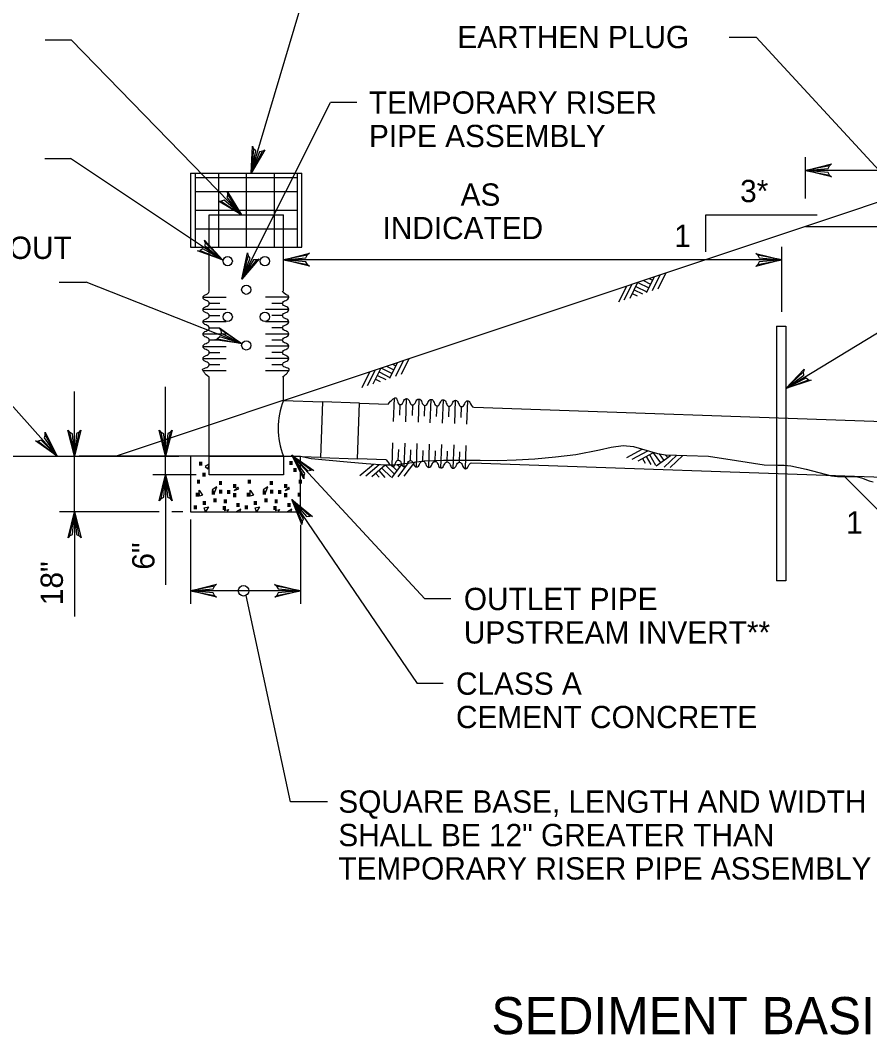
# Model space of a CAD drawing. Extents: x 636462 to 639890, y 299944 to 300538.
# Drawn here: x 638284.1 to 638398.4, y 300298.5 to 300434.9 of the extents above; entities that cross this region are included whole.
import ezdxf

# ---------------------------------------------------------------- set-up
doc = ezdxf.new("R2010")
doc.units = 0
doc.layers.add('Default', color=7, linetype='Continuous')

msp = doc.modelspace()

# ---------------------------------------------------------------- linework, layer by layer
at = {"layer": 'Default'}
for p, q in [((638315.17, 300414.4), (638326.63, 300452.77)), ((638379.5, 300432.69), (638383.11, 300432.69)), ((638399.69, 300414.74), (638383.11, 300432.69)), ((638287.46, 300432.33), (638290.96, 300432.33)), ((638313.87, 300408.78), (638290.96, 300432.33)), ((638313.89, 300400.13), (638325.85, 300423.89)), ((638329.39, 300423.89), (638325.85, 300423.89)), ((638287.41, 300416.33), (638290.85, 300416.33)), ((638311.33, 300402.72), (638290.85, 300416.33)), ((638389.77, 300410.96), (638389.77, 300416.55)), ((638409.6, 300414.74), (638389.77, 300414.74)), ((638307.01, 300414.4), (638322, 300414.4)), ((638307.01, 300414.4), (638307.01, 300404.41)), ((638307.64, 300414.4), (638307.64, 300404.41)), ((638307.64, 300413.78), (638321.38, 300413.78)), ((638310.76, 300414.4), (638310.76, 300404.41)), ((638314.51, 300414.4), (638314.51, 300404.41)), ((638318.26, 300414.4), (638318.26, 300404.41)), ((638321.38, 300404.41), (638321.38, 300414.4)), ((638322, 300404.41), (638322, 300414.4)), ((638307.64, 300411.91), (638321.38, 300411.91)), ((638307.64, 300409.41), (638321.38, 300409.41)), ((638309.51, 300398.49), (638309.51, 300408.78)), ((638309.51, 300408.78), (638319.5, 300408.78)), ((638319.5, 300398.51), (638319.5, 300408.78)), ((638307.64, 300406.91), (638321.38, 300406.91)), ((638307.01, 300404.41), (638322, 300404.41)), ((638319.5, 300400.26), (638319.5, 300404.46)), ((638386.56, 300395.74), (638386.56, 300404.46)), ((638386.56, 300402.71), (638319.5, 300402.71)), ((638289.35, 300399.72), (638292.94, 300399.72)), ((638313.85, 300391.48), (638292.94, 300399.72)), ((638366.15, 300397.57), (638367.21, 300399.7)), ((638367.18, 300399.69), (638368.68, 300398.94)), ((638367.95, 300399.95), (638368.92, 300399.46)), ((638368.36, 300398.31), (638369.43, 300400.45)), ((638368.72, 300400.21), (638369.19, 300399.97)), ((638369.17, 300398.58), (638370.22, 300400.69)), ((638369.94, 300398.84), (638370.99, 300400.94)), ((638364.64, 300397.07), (638365.7, 300399.19)), ((638365.38, 300397.32), (638366.44, 300399.45)), ((638366.7, 300398.69), (638367.82, 300398.13)), ((638366.93, 300399.15), (638368.4, 300398.41)), ((638387.1, 300385.4), (638408.53, 300398.44)), ((638311.82, 300397.67), (638308.69, 300397.67)), ((638320.22, 300397.68), (638317.09, 300397.68)), ((638366.45, 300398.18), (638367.09, 300397.86)), ((638311.82, 300396.02), (638308.69, 300396.02)), ((638310.95, 300396.84), (638309.51, 300396.84)), ((638320.22, 300396.03), (638317.09, 300396.03)), ((638319.4, 300396.86), (638317.96, 300396.86)), ((638311.82, 300394.37), (638308.69, 300394.37)), ((638310.95, 300395.19), (638309.51, 300395.19)), ((638320.22, 300394.39), (638317.09, 300394.39)), ((638319.4, 300395.21), (638317.96, 300395.21)), ((638310.95, 300393.54), (638309.51, 300393.54)), ((638319.4, 300393.56), (638317.96, 300393.56)), ((638385.85, 300393.79), (638387.1, 300393.79)), ((638385.85, 300393.79), (638385.85, 300359.54)), ((638387.1, 300393.79), (638387.1, 300359.54)), ((638311.82, 300392.72), (638308.69, 300392.72)), ((638310.95, 300391.89), (638309.51, 300391.89)), ((638320.22, 300392.74), (638317.09, 300392.74)), ((638319.4, 300391.91), (638317.96, 300391.91)), ((638308.69, 300391.07), (638311.82, 300391.07)), ((638309.51, 300390.24), (638310.95, 300390.24)), ((638320.22, 300391.09), (638317.09, 300391.09)), ((638319.4, 300390.26), (638317.96, 300390.26)), ((638311.82, 300389.42), (638308.69, 300389.42)), ((638320.22, 300389.44), (638317.09, 300389.44)), ((638333.81, 300386.8), (638334.88, 300388.93)), ((638334.17, 300388.69), (638334.64, 300388.46)), ((638334.62, 300387.07), (638335.67, 300389.17)), ((638335.39, 300387.32), (638336.44, 300389.43)), ((638311.82, 300387.77), (638308.69, 300387.77)), ((638310.95, 300388.6), (638309.51, 300388.6)), ((638320.22, 300387.79), (638317.09, 300387.79)), ((638319.4, 300388.61), (638317.96, 300388.61)), ((638330.09, 300385.55), (638331.15, 300387.67)), ((638330.83, 300385.8), (638331.9, 300387.93)), ((638331.6, 300386.06), (638332.66, 300388.19)), ((638332.39, 300387.63), (638333.85, 300386.9)), ((638332.63, 300388.17), (638334.13, 300387.42)), ((638333.4, 300388.43), (638334.38, 300387.94)), ((638309.51, 300376.3), (638309.51, 300386.95)), ((638319.5, 300383.8), (638319.5, 300386.97)), ((638331.9, 300386.66), (638332.54, 300386.34)), ((638332.16, 300387.17), (638333.27, 300386.62)), ((638291.38, 300368.81), (638291.38, 300385.01)), ((638303.66, 300373.81), (638303.66, 300385.62)), ((638289.06, 300376.3), (638282.07, 300384.14)), ((638319.45, 300383.78), (638309.51, 300380.47)), ((638319.5, 300383.8), (638324.76, 300383.62)), ((638329.75, 300383.45), (638333.59, 300383.31)), ((638334.33, 300380.98), (638334.44, 300384.11)), ((638335.18, 300381.82), (638335.23, 300383.25)), ((638335.98, 300380.92), (638336.09, 300384.05)), ((638337.73, 300383.99), (638337.62, 300380.86)), ((638339.27, 300380.8), (638339.38, 300383.93)), ((638340.92, 300380.75), (638341.03, 300383.88)), ((638342.57, 300380.69), (638342.68, 300383.82)), ((638344.21, 300380.63), (638344.32, 300383.76)), ((638336.88, 300383.2), (638336.83, 300381.76)), ((638338.48, 300381.7), (638338.53, 300383.14)), ((638340.13, 300381.64), (638340.18, 300383.08)), ((638341.77, 300381.59), (638341.82, 300383.02)), ((638343.42, 300381.53), (638343.47, 300382.97)), ((638345.12, 300382.91), (638458.99, 300378.93)), ((638309.51, 300380.47), (638297.02, 300376.3)), ((638334.12, 300374.97), (638334.23, 300378.1)), ((638335.77, 300374.91), (638335.88, 300378.04)), ((638337.41, 300374.85), (638337.52, 300377.99)), ((638339.06, 300374.8), (638339.17, 300377.93)), ((638340.71, 300374.74), (638340.82, 300377.87)), ((638342.36, 300374.68), (638342.47, 300377.81)), ((638320.64, 300376.46), (638338.54, 300357.1)), ((638334.97, 300375.76), (638335.02, 300377.2)), ((638336.62, 300375.71), (638336.67, 300377.14)), ((638338.27, 300375.65), (638338.32, 300377.09)), ((638339.91, 300375.59), (638339.96, 300377.03)), ((638341.56, 300375.53), (638341.61, 300376.97)), ((638343.21, 300375.48), (638343.26, 300376.91)), ((638344.01, 300374.62), (638344.11, 300377.75)), ((638365.71, 300376.12), (638367.78, 300377.26)), ((638366.46, 300375.9), (638368.55, 300377.04)), ((638367.24, 300375.67), (638369.32, 300376.82)), ((638368.78, 300376.52), (638369.58, 300375.08)), ((638369.28, 300376.76), (638370.26, 300375.4)), ((638370.07, 300376.63), (638370.71, 300375.74)), ((638370.75, 300374.81), (638372.45, 300376.43)), ((638370.88, 300376.49), (638371.24, 300376.12)), ((638371.56, 300374.79), (638373.26, 300376.41)), ((638280.08, 300376.3), (638305.45, 300376.3)), ((638307.76, 300376.3), (638292.04, 300376.3)), ((638309.51, 300375.23), (638308.98, 300374.9)), ((638309.32, 300374.6), (638309.51, 300375.09)), ((638324.5, 300376.13), (638319.5, 300376.3)), ((638333.32, 300375.82), (638329.49, 300375.96)), ((638329.81, 300373.71), (638331.62, 300375.24)), ((638330.59, 300373.65), (638332.41, 300375.18)), ((638331.4, 300373.58), (638333.21, 300375.12)), ((638333.18, 300375.12), (638334.39, 300373.95)), ((638333.99, 300375.13), (638334.77, 300374.37)), ((638334.1, 300373.39), (638335.54, 300375.3)), ((638334.8, 300375.18), (638335.22, 300374.87)), ((638334.95, 300373.51), (638336.36, 300375.39)), ((638335.75, 300373.62), (638337.17, 300375.5)), ((638344.86, 300375.42), (638458.72, 300371.44)), ((638367.83, 300376), (638368.17, 300375.37)), ((638368.34, 300376.27), (638368.94, 300375.18)), ((638369.68, 300374.99), (638371.62, 300376.39)), ((638307.76, 300373.81), (638301.92, 300373.81)), ((638303.66, 300373.81), (638303.66, 300359.02)), ((638308.98, 300374.9), (638309.32, 300374.6)), ((638331.91, 300374.01), (638332.37, 300373.47)), ((638332.35, 300374.38), (638333.15, 300373.43)), ((638332.78, 300374.67), (638333.96, 300373.53)), ((638320.64, 300370.47), (638337.49, 300345.71)), ((638302.77, 300368.81), (638289.39, 300368.81)), ((638291.38, 300368.81), (638291.38, 300354.76)), ((638305.96, 300368.81), (638304.5, 300368.81)), ((638308.85, 300369.36), (638309.44, 300369.48)), ((638309.01, 300368.81), (638308.85, 300369.36)), ((638309.44, 300369.48), (638309.03, 300368.81)), ((638311.55, 300369), (638312.13, 300369.11)), ((638312.13, 300369.11), (638311.95, 300368.81)), ((638313.78, 300369.17), (638313.2, 300368.81)), ((638313.64, 300368.81), (638313.78, 300369.17)), ((638315.71, 300369.36), (638316.29, 300369.48)), ((638315.87, 300368.81), (638315.71, 300369.36)), ((638316.29, 300369.48), (638315.89, 300368.81)), ((638318.41, 300369), (638318.99, 300369.11)), ((638318.99, 300369.11), (638318.81, 300368.81)), ((638320.64, 300369.17), (638320.06, 300368.81)), ((638320.5, 300368.81), (638320.64, 300369.17)), ((638307.01, 300367.8), (638307.01, 300356.45)), ((638321.82, 300367.06), (638321.82, 300356.45)), ((638387.1, 300359.54), (638385.85, 300359.54)), ((638321.82, 300358.2), (638307.01, 300358.2)), ((638342.04, 300357.1), (638338.54, 300357.1)), ((638340.99, 300345.71), (638337.49, 300345.71))]:
    msp.add_line(p, q, dxfattribs=at)
for points in [[(638316.71, 300417.32), (638317, 300417.51), (638315.17, 300414.4), (638316.71, 300417.32), (638316.3, 300417.23), (638315.17, 300414.4), (638315.8, 300417.38), (638315.49, 300417.66), (638315.17, 300414.4), (638315.33, 300418.01), (638315.49, 300417.66)], [(638319.5, 300383.8), (638413.19, 300415.03), (638434.43, 300415.03), (638455.67, 300415.03)], [(638393, 300414.1), (638393.27, 300413.88), (638389.77, 300414.74), (638393, 300414.1), (638392.81, 300414.48), (638389.77, 300414.74), (638392.8, 300415), (638392.98, 300415.38), (638389.77, 300414.74), (638393.27, 300415.63), (638392.98, 300415.38)], [(638312.02, 300411.51), (638311.99, 300411.86), (638313.87, 300408.78), (638312.02, 300411.51), (638311.9, 300411.11), (638313.87, 300408.78), (638311.53, 300410.73), (638311.14, 300410.6), (638313.87, 300408.78), (638310.76, 300410.61), (638311.14, 300410.6)], [(638376.36, 300403.78), (638376.36, 300408.77), (638391.35, 300408.77)], [(638389.77, 300407.22), (638434.43, 300407.22), (638479.09, 300407.22)], [(638308.99, 300405.04), (638308.89, 300405.37), (638311.33, 300402.72), (638308.99, 300405.04), (638308.95, 300404.62), (638311.33, 300402.72), (638308.66, 300404.18), (638308.3, 300403.96), (638311.33, 300402.72), (638307.93, 300403.91), (638308.3, 300403.96)], [(638315.92, 300402.73), (638316.24, 300402.86), (638313.89, 300400.13), (638315.92, 300402.73), (638315.5, 300402.72), (638313.89, 300400.13), (638315.03, 300402.95), (638314.78, 300403.28), (638313.89, 300400.13), (638314.68, 300403.65), (638314.78, 300403.28)], [(638322.74, 300402.07), (638323.01, 300401.85), (638319.5, 300402.71), (638322.74, 300402.07), (638322.54, 300402.45), (638319.5, 300402.71), (638322.53, 300402.97), (638322.72, 300403.34), (638319.5, 300402.71), (638323, 300403.6), (638322.72, 300403.34)], [(638383.33, 300403.35), (638383.06, 300403.57), (638386.56, 300402.71), (638383.33, 300403.35), (638383.53, 300402.97), (638386.56, 300402.71), (638383.53, 300402.45), (638383.35, 300402.08), (638386.56, 300402.71), (638383.07, 300401.82), (638383.35, 300402.08)], [(638311.09, 300393.28), (638310.92, 300393.59), (638313.85, 300391.48), (638311.09, 300393.28), (638311.13, 300392.86), (638313.85, 300391.48), (638310.94, 300392.37), (638310.63, 300392.09), (638313.85, 300391.48), (638310.27, 300391.96), (638310.63, 300392.09)], [(638390.19, 300386.56), (638390.53, 300386.52), (638387.1, 300385.4), (638390.19, 300386.56), (638389.82, 300386.78), (638387.1, 300385.4), (638389.54, 300387.22), (638389.5, 300387.63), (638387.1, 300385.4), (638389.6, 300388), (638389.5, 300387.63)], [(638287.46, 300379.18), (638287.45, 300379.53), (638289.06, 300376.3), (638287.46, 300379.18), (638287.3, 300378.79), (638289.06, 300376.3), (638286.91, 300378.45), (638286.5, 300378.34), (638289.06, 300376.3), (638286.13, 300378.39), (638286.5, 300378.34)], [(638292.02, 300379.54), (638292.24, 300379.81), (638291.38, 300376.3), (638292.02, 300379.54), (638291.64, 300379.34), (638291.38, 300376.3), (638291.12, 300379.33), (638290.74, 300379.52), (638291.38, 300376.3), (638290.49, 300379.8), (638290.74, 300379.52)], [(638304.3, 300379.54), (638304.53, 300379.81), (638303.66, 300376.3), (638304.3, 300379.54), (638303.93, 300379.34), (638303.66, 300376.3), (638303.41, 300379.33), (638303.03, 300379.52), (638303.66, 300376.3), (638302.78, 300379.8), (638303.03, 300379.52)], [(638319.5, 300376.3), (638321.82, 300376.3), (638323.22, 300375.98), (638325.65, 300375.77), (638328.08, 300375.55), (638330.64, 300375.33), (638333.19, 300375.12), (638334.51, 300375.14), (638338.47, 300375.7), (638341.03, 300375.76), (638343.6, 300375.78), (638345.97, 300375.76), (638348.34, 300375.74), (638350.85, 300375.81), (638353.35, 300375.95), (638356.12, 300376.21), (638358.88, 300376.53), (638362.05, 300377.17), (638363.63, 300377.51), (638365.21, 300377.72), (638366.64, 300377.6), (638368.78, 300376.97), (638369.85, 300376.67), (638370.93, 300376.49), (638373.81, 300376.41), (638376.7, 300376.29), (638380.46, 300375.71), (638384.22, 300375.13), (638386.02, 300375.1), (638386.91, 300375.1), (638387.8, 300375.01), (638388.83, 300374.79), (638389.84, 300374.55), (638391.55, 300374.1), (638393.27, 300373.66), (638394.09, 300373.56), (638396.6, 300373.55), (638397.3, 300373.38), (638398.34, 300373.01), (638398.86, 300372.87)], [(638322.25, 300373.59), (638322.26, 300373.24), (638320.64, 300376.46), (638322.25, 300373.59), (638322.41, 300373.98), (638320.64, 300376.46), (638322.8, 300374.33), (638323.21, 300374.43), (638320.64, 300376.46), (638323.58, 300374.38), (638323.21, 300374.43)], [(638319.5, 300376.3), (638307.01, 300376.3), (638307.01, 300368.81), (638321.82, 300368.81), (638321.82, 300376.22), (638319.5, 300376.3)], [(638303.03, 300370.57), (638302.8, 300370.3), (638303.66, 300373.81), (638303.03, 300370.57), (638303.4, 300370.77), (638303.66, 300373.81), (638303.92, 300370.78), (638304.3, 300370.59), (638303.66, 300373.81), (638304.55, 300370.31), (638304.3, 300370.59)], [(638460.66, 300370.83), (638449.18, 300359.35), (638409.21, 300359.35), (638395, 300373.55)], [(638322.02, 300367.48), (638322, 300367.13), (638320.64, 300370.47), (638322.02, 300367.48), (638322.21, 300367.86), (638320.64, 300370.47), (638322.63, 300368.17), (638323.04, 300368.25), (638320.64, 300370.47), (638323.41, 300368.17), (638323.04, 300368.25)], [(638290.74, 300365.58), (638290.52, 300365.31), (638291.38, 300368.81), (638290.74, 300365.58), (638291.11, 300365.77), (638291.38, 300368.81), (638291.64, 300365.78), (638292.01, 300365.6), (638291.38, 300368.81), (638292.27, 300365.31), (638292.01, 300365.6)], [(638310.24, 300357.57), (638310.51, 300357.34), (638307.01, 300358.2), (638310.24, 300357.57), (638310.05, 300357.94), (638307.01, 300358.2), (638310.04, 300358.46), (638310.22, 300358.84), (638307.01, 300358.2), (638310.51, 300359.09), (638310.22, 300358.84)], [(638318.59, 300358.84), (638318.32, 300359.06), (638321.82, 300358.2), (638318.59, 300358.84), (638318.79, 300358.47), (638321.82, 300358.2), (638318.79, 300357.94), (638318.61, 300357.57), (638321.82, 300358.2), (638318.33, 300357.32), (638318.61, 300357.57)], [(638325.46, 300329.82), (638320.46, 300329.82), (638314.48, 300357.58)]]:
    msp.add_lwpolyline(points, dxfattribs=at)
for points in [[(638324.76, 300383.62), (638324.5, 300376.13), (638329.49, 300375.96), (638329.75, 300383.45)], [(638319.5, 300376.3), (638319.5, 300373.81), (638309.51, 300373.81), (638309.51, 300376.3)], [(638308.63, 300371.04), (638308.2, 300370.94), (638308.18, 300371.73)], [(638310.53, 300372.16), (638309.93, 300371.79), (638310.27, 300371.48)], [(638313.49, 300371.91), (638313.38, 300372.15), (638312.87, 300371.7)], [(638315.49, 300371.04), (638315.05, 300370.94), (638315.04, 300371.73)], [(638317.39, 300372.16), (638316.79, 300371.79), (638317.12, 300371.48)], [(638320.34, 300371.91), (638320.24, 300372.15), (638319.72, 300371.7)]]:
    msp.add_lwpolyline(points, close=True, dxfattribs=at)
for centre, radius in [((638312.01, 300402.54), 0.625), ((638317.01, 300402.54), 0.625), ((638314.51, 300398.7), 0.625), ((638312.01, 300395.04), 0.625), ((638317.01, 300395.04), 0.625), ((638314.51, 300391.21), 0.625), ((638314.14, 300358.2), 0.708)]:
    msp.add_circle(centre, radius, dxfattribs=at)
msp.add_arc((638328.67, 300380.03), 9.89, 157.6174, 202.1206, dxfattribs=at)
for points in [[(638309.51, 300386.95), (638309.14, 300387.22), (638308.88, 300387.5), (638308.69, 300387.77), (638308.49, 300388.05), (638309.51, 300388.32), (638309.51, 300388.6), (638309.51, 300388.87), (638308.69, 300389.15), (638308.69, 300389.42), (638308.69, 300389.7), (638309.51, 300389.97), (638309.51, 300390.24), (638309.51, 300390.52), (638308.69, 300390.79), (638308.69, 300391.07), (638308.69, 300391.34), (638309.51, 300391.62), (638309.51, 300391.89), (638309.51, 300392.17), (638308.69, 300392.44), (638308.69, 300392.72), (638308.69, 300392.99), (638309.51, 300393.27), (638309.51, 300393.54), (638309.51, 300393.82), (638308.69, 300394.09), (638308.69, 300394.37), (638308.69, 300394.64), (638309.51, 300394.92), (638309.51, 300395.19), (638309.51, 300395.47), (638308.69, 300395.74), (638308.69, 300396.02), (638308.69, 300396.29), (638309.51, 300396.57), (638309.51, 300396.84), (638309.51, 300397.12), (638308.69, 300397.39), (638308.69, 300397.67), (638308.69, 300397.94), (638309.56, 300398.21), (638309.51, 300398.49)], [(638319.4, 300386.97), (638319.76, 300387.24), (638320.03, 300387.52), (638320.22, 300387.79), (638320.42, 300388.07), (638319.4, 300388.34), (638319.4, 300388.61), (638319.4, 300388.89), (638320.22, 300389.16), (638320.22, 300389.44), (638320.22, 300389.71), (638319.4, 300389.99), (638319.4, 300390.26), (638319.4, 300390.54), (638320.22, 300390.81), (638320.22, 300391.09), (638320.22, 300391.36), (638319.4, 300391.64), (638319.4, 300391.91), (638319.4, 300392.19), (638320.22, 300392.46), (638320.22, 300392.74), (638320.22, 300393.01), (638319.4, 300393.29), (638319.4, 300393.56), (638319.4, 300393.84), (638320.22, 300394.11), (638320.22, 300394.39), (638320.22, 300394.66), (638319.4, 300394.94), (638319.4, 300395.21), (638319.4, 300395.49), (638320.22, 300395.76), (638320.22, 300396.03), (638320.22, 300396.31), (638319.4, 300396.58), (638319.4, 300396.86), (638319.4, 300397.13), (638320.22, 300397.41), (638320.22, 300397.68), (638320.22, 300397.96), (638319.4, 300398.23), (638319.4, 300398.51)], [(638333.59, 300383.31), (638333.87, 300383.67), (638334.16, 300383.92), (638334.44, 300384.11), (638334.72, 300384.29), (638334.96, 300383.26), (638335.23, 300383.25), (638335.51, 300383.24), (638335.81, 300384.06), (638336.09, 300384.05), (638336.36, 300384.04), (638336.61, 300383.21), (638336.88, 300383.2), (638337.15, 300383.19), (638337.46, 300384), (638337.73, 300383.99), (638338.01, 300383.98), (638338.25, 300383.15), (638338.53, 300383.14), (638338.8, 300383.13), (638339.11, 300383.94), (638339.38, 300383.93), (638339.66, 300383.92), (638339.9, 300383.09), (638340.18, 300383.08), (638340.45, 300383.07), (638340.75, 300383.89), (638341.03, 300383.88), (638341.3, 300383.87), (638341.55, 300383.03), (638341.82, 300383.02), (638342.1, 300383.01), (638342.4, 300383.83), (638342.68, 300383.82), (638342.95, 300383.81), (638343.2, 300382.98), (638343.47, 300382.97), (638343.75, 300382.96), (638344.05, 300383.77), (638344.32, 300383.76), (638344.6, 300383.75), (638344.84, 300382.87), (638345.12, 300382.91)], [(638333.32, 300375.82), (638333.59, 300375.45), (638333.85, 300375.17), (638334.12, 300374.97), (638334.39, 300374.76), (638334.7, 300375.77), (638334.97, 300375.76), (638335.25, 300375.75), (638335.49, 300374.92), (638335.77, 300374.91), (638336.04, 300374.9), (638336.34, 300375.72), (638336.62, 300375.71), (638336.89, 300375.7), (638337.14, 300374.86), (638337.41, 300374.85), (638337.69, 300374.84), (638337.99, 300375.66), (638338.27, 300375.65), (638338.54, 300375.64), (638338.79, 300374.81), (638339.06, 300374.8), (638339.34, 300374.79), (638339.64, 300375.6), (638339.91, 300375.59), (638340.19, 300375.58), (638340.43, 300374.75), (638340.71, 300374.74), (638340.98, 300374.73), (638341.29, 300375.54), (638341.56, 300375.53), (638341.84, 300375.52), (638342.08, 300374.69), (638342.36, 300374.68), (638342.63, 300374.67), (638342.94, 300375.49), (638343.21, 300375.48), (638343.48, 300375.47), (638343.73, 300374.63), (638344.01, 300374.62), (638344.28, 300374.61), (638344.58, 300375.43), (638344.86, 300375.42)]]:
    msp.add_open_spline(points, degree=3, dxfattribs=at)

# ---------------------------------------------------------------- texts
for s, height, p in [('EARTHEN PLUG', 2.998, (638342.91, 300431.2)), ('TEMPORARY RISER', 2.998, (638331.02, 300422.38)), ('PIPE ASSEMBLY', 2.998, (638331.02, 300417.88)), ('3*', 2.998, (638380.97, 300410.48)), ('AS', 2.998, (638343.35, 300410)), ('INDICATED', 2.998, (638332.85, 300405.5)), ('1', 3, (638372.1, 300404.45)), ('BASIN CLEAN OUT', 2.998, (638254.93, 300402.84)), ('.', 3.5, (638307.74, 300375.01)), ('.', 3.5, (638319.88, 300375.13)), ('.', 3.5, (638308.15, 300373.54)), ('.', 3.5, (638320.43, 300374.19)), ('.', 3.5, (638307.43, 300372.6)), ('.', 3.5, (638310.39, 300372.42)), ('.', 3.5, (638312.3, 300372.02)), ('.', 3.5, (638314.29, 300372.6)), ('.', 3.5, (638317.25, 300372.42)), ('.', 3.5, (638319.16, 300372.02)), ('.', 3.5, (638321.14, 300372.6)), ('.', 3.5, (638307.28, 300370.87)), ('.', 3.5, (638309.42, 300371.13)), ('.', 3.5, (638310.42, 300371.25)), ('.', 3.5, (638311.48, 300371.21)), ('.', 3.5, (638312.3, 300370.79)), ('.', 3.5, (638314.14, 300370.87)), ('.', 3.5, (638316.28, 300371.13)), ('.', 3.5, (638317.28, 300371.25)), ('.', 3.5, (638318.34, 300371.21)), ('.', 3.5, (638319.16, 300370.79)), ('.', 3.5, (638320.99, 300370.87)), ('.', 3.5, (638307.01, 300369.16)), ('.', 3.5, (638308.21, 300369.72)), ('.', 3.5, (638309.65, 300370.11)), ('.', 3.5, (638310.89, 300369.08)), ('.', 3.5, (638310.89, 300369.08)), ('.', 3.5, (638311.02, 300369.97)), ('.', 3.5, (638312.73, 300369.46)), ('.', 3.5, (638313.86, 300369.16)), ('.', 3.5, (638315.06, 300369.72)), ('.', 3.5, (638316.5, 300370.11)), ('.', 3.5, (638317.74, 300369.08)), ('.', 3.5, (638317.74, 300369.08)), ('.', 3.5, (638317.88, 300369.97)), ('.', 3.5, (638319.59, 300369.46)), ('.', 3.5, (638320.72, 300369.16)), ('1', 3, (638395.23, 300365.89)), ('OUTLET PIPE', 2.998, (638343.79, 300355.6)), ('UPSTREAM INVERT**', 2.998, (638343.79, 300351.1)), ('CLASS A', 2.998, (638342.73, 300344.21)), ('CEMENT CONCRETE', 2.998, (638342.73, 300339.72)), ('SQUARE BASE, LENGTH AND WIDTH', 2.998, (638326.9, 300328.34)), ('SHALL BE 12" GREATER THAN', 2.998, (638326.9, 300323.84)), ('TEMPORARY RISER PIPE ASSEMBLY DIAMETER', 2.998, (638326.9, 300319.35)), ('SEDIMENT BASIN - TEMPORARY CONFIGURATION', 4.9967, (638347.49, 300298.55))]:
    msp.add_text(s, height=height, dxfattribs=at).set_placement(p)
for s, p in [('6"', (638302.15, 300361.04)), ('18"', (638289.83, 300356.27))]:
    msp.add_text(s, height=2.998, rotation=90, dxfattribs=at).set_placement(p)

doc.saveas('drawing.dxf')
